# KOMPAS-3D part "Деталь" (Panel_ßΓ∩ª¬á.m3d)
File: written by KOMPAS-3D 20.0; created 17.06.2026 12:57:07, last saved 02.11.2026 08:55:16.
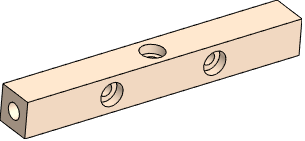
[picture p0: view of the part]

Document properties: Полное имя файла: D:\RicWork\Project-EPS32\box_compas\корпус\Panel_стяжка.m3d

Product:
- Part/product: Деталь
    Масса: 0.0499424

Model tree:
1. Эскиз:2
2. Элемент выдавливания:1
     Расстояние 1 = 80
3. Эскиз:3  (with: Элемент выдавливания:1)
4. Элемент выдавливания:2
     Расстояние 2 = 20
5. Эскиз:4  (with: Элемент выдавливания:1)
6. Элемент выдавливания:3
     Расстояние 2 = 20
7. Эскиз:5  (with: Элемент выдавливания:1)
8. Элемент выдавливания:4
     Расстояние 2 = 9
9. Эскиз:6  (with: Элемент выдавливания:1)
10. Элемент выдавливания:5
     Расстояние 2 = 10
11. Скругление:1  (with: Элемент выдавливания:4)
     Радиус = 1.5
12. Эскиз:8  (with: Элемент выдавливания:1)
13. Элемент выдавливания:6
     Расстояние 2 = 10
14. Эскиз:9  (with: Элемент выдавливания:1)
15. Элемент выдавливания:7
     Расстояние 2 = 2.5
16. Эскиз:10  (with: Элемент выдавливания:1)
17. Элемент выдавливания:8
     Расстояние 2 = 2.5
18. Эскиз:11  (with: Элемент выдавливания:1, Элемент выдавливания:6)
19. Элемент выдавливания:9
     Расстояние 2 = 2.5
20. Эскиз:12  (with: Элемент выдавливания:1)
21. Элемент выдавливания:10
     Расстояние 2 = 2.5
